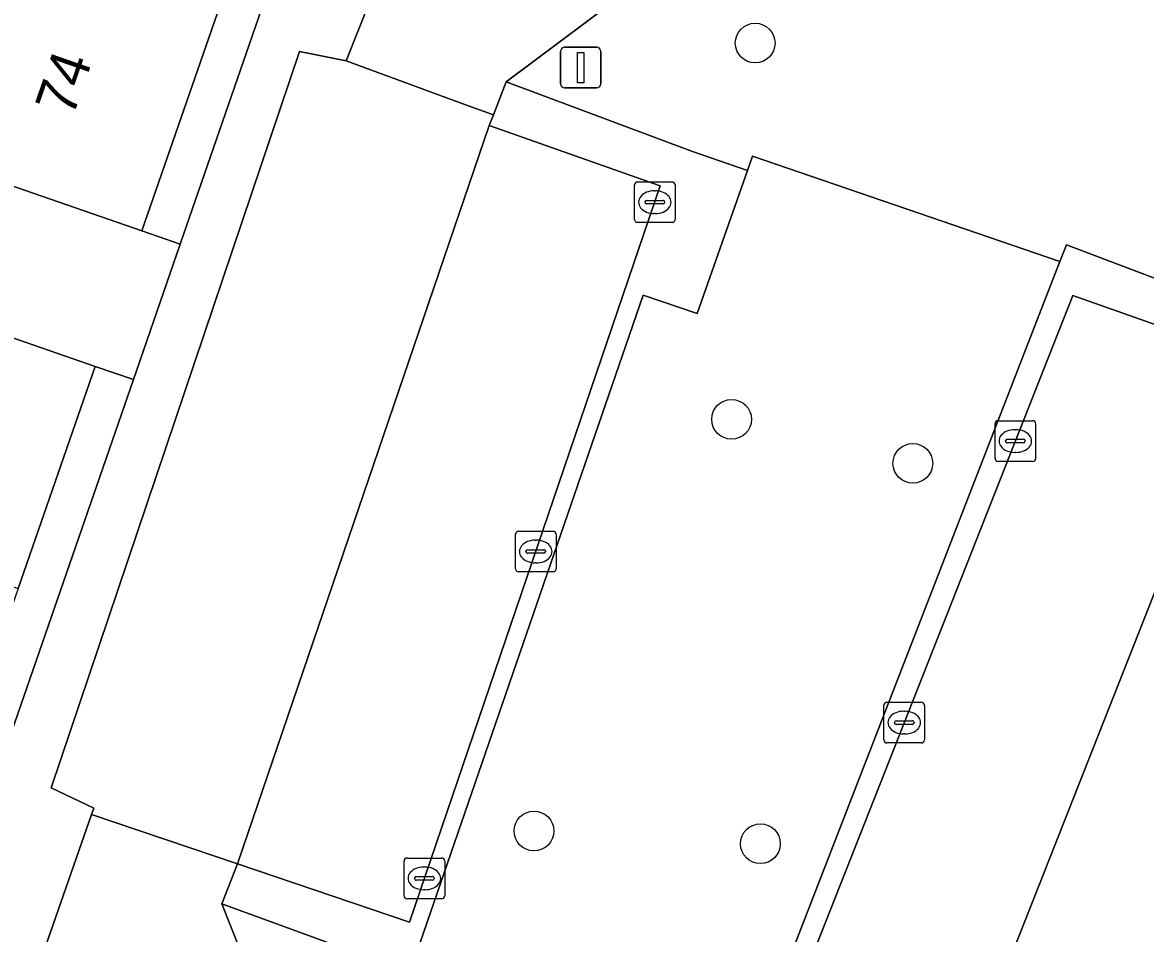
# Model space of a CAD drawing. Extents: x 160349 to 161355, y 381727 to 382854.
# Drawn here: x 160652.39 to 160680.04, y 382152.84 to 382175.26 of the extents above; entities that cross this region are included whole.
import ezdxf

# ---------------------------------------------------------------- set-up
doc = ezdxf.new("R2010")
doc.units = 0
for name, color, linetype in [('IMGEO_Boom', 7, 'Continuous'), ('IMGEO_Erf', 7, 'Continuous'), ('IMGEO_Groenvoorziening', 7, 'Continuous'), ('IMGEO_Kolk', 7, 'Continuous'), ('IMGEO_Lichtmast', 7, 'Continuous'), ('IMGEO_Pand', 7, 'Continuous'), ('IMGEO_Pand_nummerreeks', 7, 'Continuous'), ('IMGEO_Parkeervlak_open', 7, 'Continuous'), ('IMGEO_Voetpad_open', 7, 'Continuous'), ('IMGEO_Woonerf_open', 7, 'Continuous')]:
    doc.layers.add(name, color=color, linetype=linetype)

msp = doc.modelspace()

# ---------------------------------------------------------------- linework, layer by layer
at = {"layer": 'IMGEO_Boom'}
for centre in [(160670.43, 382174.75), (160669.849, 382165.491), (160674.313, 382164.408), (160664.983, 382155.361), (160670.559, 382155.048)]:
    msp.add_circle(centre, 0.489, dxfattribs=at)
at = {"layer": 'IMGEO_Erf'}
for points in [[(160678.979, 382235.356), (160678.036, 382235.688), (160676.111, 382230.13), (160674.225, 382224.686), (160672.339, 382219.241), (160670.454, 382213.797), (160668.568, 382208.352), (160666.682, 382202.907), (160664.796, 382197.463), (160662.911, 382192.019), (160661.024, 382186.573), (160659.139, 382181.129), (160657.253, 382175.684), (160655.328, 382170.127), (160656.273, 382169.8)], [(160655.119, 382166.468), (160654.174, 382166.795), (160652.281, 382161.329), (160650.426, 382155.975), (160648.573, 382150.623), (160646.719, 382145.27), (160644.864, 382139.917), (160643.011, 382134.564), (160641.156, 382129.211), (160639.302, 382123.858), (160637.448, 382118.505), (160635.594, 382113.151), (160633.702, 382107.689), (160634.64, 382107.343), (160634.794, 382107.787)]]:
    msp.add_lwpolyline(points, close=True, dxfattribs=at)
at = {"layer": 'IMGEO_Groenvoorziening'}
for points in [[(160693.185, 382201.839), (160694.059, 382204.062), (160684.663, 382209.401), (160685.334, 382210.118), (160686.362, 382212.23), (160683.428, 382213.325), (160677.237, 382195.926), (160674.564, 382196.99), (160673.941, 382194.938), (160673.693, 382194.029), (160667.606, 382176.272), (160664.299, 382173.795), (160668.888, 382172.08), (160670.241, 382171.613), (160670.367, 382171.963), (160677.936, 382169.378), (160678.093, 382169.781), (160680.44, 382168.899), (160689.732, 382192.872)], [(160677.263, 382167.644), (160677.936, 382169.378), (160670.367, 382171.963), (160670.241, 382171.613), (160668.998, 382168.093), (160667.671, 382168.55), (160661.924, 382151.879), (160657.296, 382153.565), (160658.593, 382150.306), (160670.649, 382150.626)]]:
    msp.add_lwpolyline(points, close=True, dxfattribs=at)
at = {"layer": 'IMGEO_Kolk'}
for p, q in [((160667.458, 382170.408), (160667.458, 382171.26)), ((160667.533, 382171.334), (160668.385, 382171.334)), ((160667.946, 382171.114), (160667.971, 382171.114)), ((160668.459, 382171.26), (160668.459, 382170.408)), ((160667.717, 382170.828), (160667.717, 382170.84)), ((160667.76, 382170.877), (160668.158, 382170.877)), ((160668.201, 382170.84), (160668.201, 382170.828)), ((160668.155, 382170.791), (160667.757, 382170.791)), ((160667.969, 382170.554), (160667.944, 382170.554)), ((160668.385, 382170.334), (160667.533, 382170.334)), ((160676.336, 382164.531), (160676.336, 382165.383)), ((160676.411, 382165.457), (160677.263, 382165.457)), ((160677.337, 382165.383), (160677.337, 382164.531)), ((160676.824, 382165.237), (160676.849, 382165.237)), ((160676.595, 382164.951), (160676.595, 382164.963)), ((160677.033, 382164.914), (160676.635, 382164.914)), ((160676.638, 382165), (160677.036, 382165)), ((160677.079, 382164.963), (160677.079, 382164.951)), ((160676.847, 382164.677), (160676.822, 382164.677)), ((160677.263, 382164.457), (160676.411, 382164.457)), ((160664.526, 382161.812), (160664.526, 382162.664)), ((160664.601, 382162.738), (160665.453, 382162.738)), ((160665.527, 382162.664), (160665.527, 382161.812)), ((160664.828, 382162.281), (160665.226, 382162.281)), ((160665.014, 382162.518), (160665.039, 382162.518)), ((160664.785, 382162.232), (160664.785, 382162.244)), ((160665.223, 382162.195), (160664.825, 382162.195)), ((160665.269, 382162.244), (160665.269, 382162.232)), ((160665.453, 382161.738), (160664.601, 382161.738)), ((160665.037, 382161.958), (160665.012, 382161.958)), ((160673.6, 382157.602), (160673.6, 382158.454)), ((160673.675, 382158.528), (160674.527, 382158.528)), ((160674.601, 382158.454), (160674.601, 382157.602)), ((160674.088, 382158.308), (160674.113, 382158.308)), ((160673.859, 382158.022), (160673.859, 382158.034)), ((160674.297, 382157.985), (160673.899, 382157.985)), ((160673.902, 382158.071), (160674.3, 382158.071)), ((160674.343, 382158.034), (160674.343, 382158.022)), ((160674.111, 382157.748), (160674.086, 382157.748)), ((160674.527, 382157.528), (160673.675, 382157.528)), ((160661.783, 382153.769), (160661.783, 382154.621)), ((160661.858, 382154.695), (160662.71, 382154.695)), ((160662.784, 382154.621), (160662.784, 382153.769)), ((160662.085, 382154.238), (160662.483, 382154.238)), ((160662.271, 382154.475), (160662.296, 382154.475)), ((160662.042, 382154.189), (160662.042, 382154.201)), ((160662.48, 382154.152), (160662.082, 382154.152)), ((160662.526, 382154.201), (160662.526, 382154.189)), ((160662.71, 382153.695), (160661.858, 382153.695)), ((160662.294, 382153.915), (160662.269, 382153.915))]:
    msp.add_line(p, q, dxfattribs=at)
for points in [[(160667.458, 382170.408), (160667.458, 382171.26)], [(160667.533, 382171.334), (160668.385, 382171.334)], [(160668.459, 382171.26), (160668.459, 382170.408)], [(160668.385, 382170.334), (160667.533, 382170.334)], [(160676.336, 382164.531), (160676.336, 382165.383)], [(160676.411, 382165.457), (160677.263, 382165.457)], [(160677.337, 382165.383), (160677.337, 382164.531)], [(160677.263, 382164.457), (160676.411, 382164.457)], [(160664.526, 382161.812), (160664.526, 382162.664)], [(160664.601, 382162.738), (160665.453, 382162.738)], [(160665.527, 382162.664), (160665.527, 382161.812)], [(160665.453, 382161.738), (160664.601, 382161.738)], [(160673.6, 382157.602), (160673.6, 382158.454)], [(160673.675, 382158.528), (160674.527, 382158.528)], [(160674.601, 382158.454), (160674.601, 382157.602)], [(160674.527, 382157.528), (160673.675, 382157.528)], [(160661.783, 382153.769), (160661.783, 382154.621)], [(160661.858, 382154.695), (160662.71, 382154.695)], [(160662.784, 382154.621), (160662.784, 382153.769)], [(160662.71, 382153.695), (160661.858, 382153.695)]]:
    msp.add_lwpolyline(points, dxfattribs=at)
for centre, radius, start, end in [((160667.535, 382171.258), 0.0765, 91.552, 178.448), ((160667.535, 382171.258), 0.0765, 91.552, 178.448), ((160668.383, 382171.258), 0.0765, 1.552, 88.448), ((160668.383, 382171.258), 0.0765, 1.552, 88.448), ((160667.757, 382170.837), 0.0403, 85.8775, 175.7526), ((160667.754, 382170.827), 0.0366, 178.938, 274.7102), ((160668.158, 382170.834), 0.043, 264.8664, 352.4533), ((160668.162, 382170.839), 0.0386, 1.7309, 96.639), ((160667.535, 382170.41), 0.0765, 181.552, 268.448), ((160667.535, 382170.41), 0.0765, 181.552, 268.448), ((160668.383, 382170.41), 0.0765, 271.552, 358.448), ((160668.383, 382170.41), 0.0765, 271.552, 358.448), ((160676.413, 382165.381), 0.0765, 91.552, 178.448), ((160676.413, 382165.381), 0.0765, 91.552, 178.448), ((160677.261, 382165.381), 0.0765, 1.552, 88.448), ((160677.261, 382165.381), 0.0765, 1.552, 88.448), ((160676.635, 382164.96), 0.0403, 85.8775, 175.7526), ((160676.632, 382164.95), 0.0366, 178.938, 274.7102), ((160677.036, 382164.957), 0.043, 264.8664, 352.4533), ((160677.04, 382164.962), 0.0386, 1.7309, 96.639), ((160676.413, 382164.533), 0.0765, 181.552, 268.448), ((160676.413, 382164.533), 0.0765, 181.552, 268.448), ((160677.261, 382164.533), 0.0765, 271.552, 358.448), ((160677.261, 382164.533), 0.0765, 271.552, 358.448), ((160664.603, 382162.662), 0.0765, 91.552, 178.448), ((160664.603, 382162.662), 0.0765, 91.552, 178.448), ((160665.451, 382162.662), 0.0765, 1.552, 88.448), ((160665.451, 382162.662), 0.0765, 1.552, 88.448), ((160664.825, 382162.241), 0.0403, 85.8775, 175.7526), ((160665.23, 382162.243), 0.0386, 1.7309, 96.639), ((160664.822, 382162.231), 0.0366, 178.938, 274.7102), ((160665.226, 382162.238), 0.043, 264.8664, 352.4533), ((160664.603, 382161.814), 0.0765, 181.552, 268.448), ((160664.603, 382161.814), 0.0765, 181.552, 268.448), ((160665.451, 382161.814), 0.0765, 271.552, 358.448), ((160665.451, 382161.814), 0.0765, 271.552, 358.448), ((160673.677, 382158.452), 0.0765, 91.552, 178.448), ((160673.677, 382158.452), 0.0765, 91.552, 178.448), ((160674.525, 382158.452), 0.0765, 1.552, 88.448), ((160674.525, 382158.452), 0.0765, 1.552, 88.448), ((160673.899, 382158.031), 0.0403, 85.8775, 175.7526), ((160673.896, 382158.021), 0.0366, 178.938, 274.7102), ((160674.3, 382158.028), 0.043, 264.8664, 352.4533), ((160674.304, 382158.033), 0.0386, 1.7309, 96.639), ((160673.677, 382157.604), 0.0765, 181.552, 268.448), ((160673.677, 382157.604), 0.0765, 181.552, 268.448), ((160674.525, 382157.604), 0.0765, 271.552, 358.448), ((160674.525, 382157.604), 0.0765, 271.552, 358.448), ((160661.86, 382154.619), 0.0765, 91.552, 178.448), ((160661.86, 382154.619), 0.0765, 91.552, 178.448), ((160662.708, 382154.619), 0.0765, 1.552, 88.448), ((160662.708, 382154.619), 0.0765, 1.552, 88.448), ((160662.082, 382154.198), 0.0403, 85.8775, 175.7526), ((160662.487, 382154.2), 0.0386, 1.7309, 96.639), ((160662.079, 382154.188), 0.0366, 178.938, 274.7102), ((160662.483, 382154.195), 0.043, 264.8664, 352.4533), ((160661.86, 382153.771), 0.0765, 181.552, 268.448), ((160661.86, 382153.771), 0.0765, 181.552, 268.448), ((160662.708, 382153.771), 0.0765, 271.552, 358.448), ((160662.708, 382153.771), 0.0765, 271.552, 358.448)]:
    msp.add_arc(centre, radius, start, end, dxfattribs=at)
for centre, major_axis, ratio, start_param, end_param in [((160667.945, 382170.834), (-0.387, 0.002), 0.722429, 4.712389, 7.853982), ((160667.97, 382170.834), (-0.39, 0.002), 0.717154, 1.570796, 4.712389), ((160676.823, 382164.957), (-0.387, 0.002), 0.722429, 4.712389, 7.853982), ((160676.848, 382164.957), (-0.39, 0.002), 0.717154, 1.570796, 4.712389), ((160665.013, 382162.238), (-0.387, 0.002), 0.722429, 4.712389, 7.853982), ((160665.038, 382162.238), (-0.39, 0.002), 0.717154, 1.570796, 4.712389), ((160674.087, 382158.028), (-0.387, 0.002), 0.722429, 4.712389, 7.853982), ((160674.112, 382158.028), (-0.39, 0.002), 0.717154, 1.570796, 4.712389), ((160662.27, 382154.195), (-0.387, 0.002), 0.722429, 4.712389, 7.853982), ((160662.295, 382154.195), (-0.39, 0.002), 0.717154, 1.570796, 4.712389)]:
    msp.add_ellipse(centre, major_axis=major_axis, ratio=ratio, start_param=start_param, end_param=end_param, dxfattribs=at)
at = {"layer": 'IMGEO_Lichtmast'}
for p, q in [((160665.637, 382173.746), (160665.637, 382174.546)), ((160665.637, 382174.546), (160665.637, 382173.746)), ((160665.737, 382174.646), (160666.527, 382174.646)), ((160666.527, 382174.646), (160665.737, 382174.646)), ((160666.627, 382174.546), (160666.627, 382173.746)), ((160666.627, 382173.746), (160666.627, 382174.546)), ((160666.527, 382173.646), (160665.737, 382173.646)), ((160665.737, 382173.646), (160666.527, 382173.646))]:
    msp.add_line(p, q, dxfattribs=at)
msp.add_lwpolyline([(160666.057, 382174.521), (160666.207, 382174.521), (160666.207, 382173.771), (160666.057, 382173.771), (160666.057, 382174.521)], dxfattribs=at)
for centre, start, end in [((160665.737, 382174.546), 90, 180), ((160665.737, 382174.546), 90, 180), ((160666.527, 382174.546), 0, 90), ((160666.527, 382174.546), 360, 90), ((160665.737, 382173.746), 180, 270), ((160665.737, 382173.746), 180, 270), ((160666.527, 382173.746), 270, 0), ((160666.527, 382173.746), 270, 0)]:
    msp.add_arc(centre, 0.1, start, end, dxfattribs=at)
at = {"layer": 'IMGEO_Pand'}
for points in [[(160657.253, 382175.684), (160649.707, 382178.302), (160647.781, 382172.741), (160650.604, 382171.763), (160655.328, 382170.127)], [(160654.174, 382166.795), (160649.45, 382168.432), (160646.842, 382169.335), (160645.861, 382166.503), (160643.02, 382167.486), (160642.107, 382164.85), (160644.948, 382163.867), (160652.281, 382161.329)]]:
    msp.add_lwpolyline(points, close=True, dxfattribs=at)
at = {"layer": 'IMGEO_Parkeervlak_open'}
for points in [[(160657.684, 382154.555), (160661.915, 382153.116), (160668.094, 382171.235), (160663.882, 382172.724)], [(160675.459, 382149.061), (160682.551, 382167.02), (160678.255, 382168.542), (160671.217, 382150.72)]]:
    msp.add_lwpolyline(points, close=True, dxfattribs=at)
at = {"layer": 'IMGEO_Voetpad_open'}
for points in [[(160682.3, 382232.389), (160678.979, 382235.356), (160656.273, 382169.8), (160655.119, 382166.468), (160634.794, 382107.787), (160639.616, 382106.019), (160640.607, 382108.902), (160638.62, 382111.527), (160640.555, 382116.871), (160639.534, 382117.379), (160643.391, 382128.676)], [(160646.738, 382138.508), (160647.308, 382140.103), (160648.749, 382139.677), (160650.485, 382144.361), (160652.241, 382143.773), (160652.976, 382143.527), (160654.244, 382147.569), (160653.938, 382148.171), (160652.456, 382151.083), (160654.086, 382155.763), (160654.142, 382155.925), (160653.091, 382156.423), (160659.21, 382174.542), (160660.36, 382174.315), (160662.127, 382178.778), (160665.361, 382180.315), (160665.451, 382180.576), (160669.634, 382192.745), (160668.197, 382195.976), (160669.486, 382199.728), (160668.101, 382200.032), (160669.967, 382205.508)], [(160627.032, 382176.536), (160627.343, 382176.418), (160632.962, 382174.283), (160646.842, 382169.335), (160649.45, 382168.432), (160654.174, 382166.795), (160655.119, 382166.468), (160656.273, 382169.8), (160655.328, 382170.127), (160650.604, 382171.763), (160647.781, 382172.741), (160634.774, 382177.3), (160630.675, 382178.72), (160628.15, 382179.595), (160630.064, 382185.117), (160631.261, 382188.569), (160632.557, 382192.224), (160633.864, 382195.996), (160635.117, 382199.609), (160636.36, 382203.416)]]:
    msp.add_lwpolyline(points, dxfattribs=at)
for points in [[(160657.684, 382154.555), (160657.296, 382153.565), (160661.924, 382151.879), (160667.671, 382168.55), (160668.998, 382168.093), (160670.241, 382171.613), (160668.888, 382172.08), (160664.299, 382173.795), (160663.984, 382172.987), (160663.882, 382172.724), (160668.094, 382171.235), (160661.915, 382153.116)], [(160680.44, 382168.899), (160678.093, 382169.781), (160677.936, 382169.378), (160677.263, 382167.644), (160670.649, 382150.626), (160670.316, 382149.77), (160675.012, 382148.08), (160675.459, 382149.061), (160671.217, 382150.72), (160678.255, 382168.542), (160682.551, 382167.02), (160683.607, 382166.646), (160683.974, 382167.572)]]:
    msp.add_lwpolyline(points, close=True, dxfattribs=at)
at = {"layer": 'IMGEO_Woonerf_open'}
for points in [[(160665.451, 382180.576), (160665.361, 382180.315), (160662.127, 382178.778), (160660.36, 382174.315), (160663.323, 382173.22), (160663.984, 382172.987), (160664.299, 382173.795), (160667.606, 382176.272)], [(160663.882, 382172.724), (160663.984, 382172.987), (160663.323, 382173.22), (160660.36, 382174.315), (160659.21, 382174.542), (160653.091, 382156.423), (160654.142, 382155.925), (160654.086, 382155.763), (160657.684, 382154.555)], [(160687.129, 382165.195), (160686.808, 382165.382), (160683.607, 382166.646), (160682.551, 382167.02), (160675.459, 382149.061), (160678.331, 382148.009), (160680.171, 382147.333)], [(160657.296, 382153.565), (160657.684, 382154.555), (160654.086, 382155.763), (160652.456, 382151.083), (160653.938, 382148.171), (160658.593, 382150.306)]]:
    msp.add_lwpolyline(points, close=True, dxfattribs=at)

# ---------------------------------------------------------------- texts
at = {"layer": 'IMGEO_Pand_nummerreeks'}
msp.add_text('74', height=1, rotation=70.8957, dxfattribs=at).set_placement((160653.623, 382172.902))

doc.saveas('drawing.dxf')
